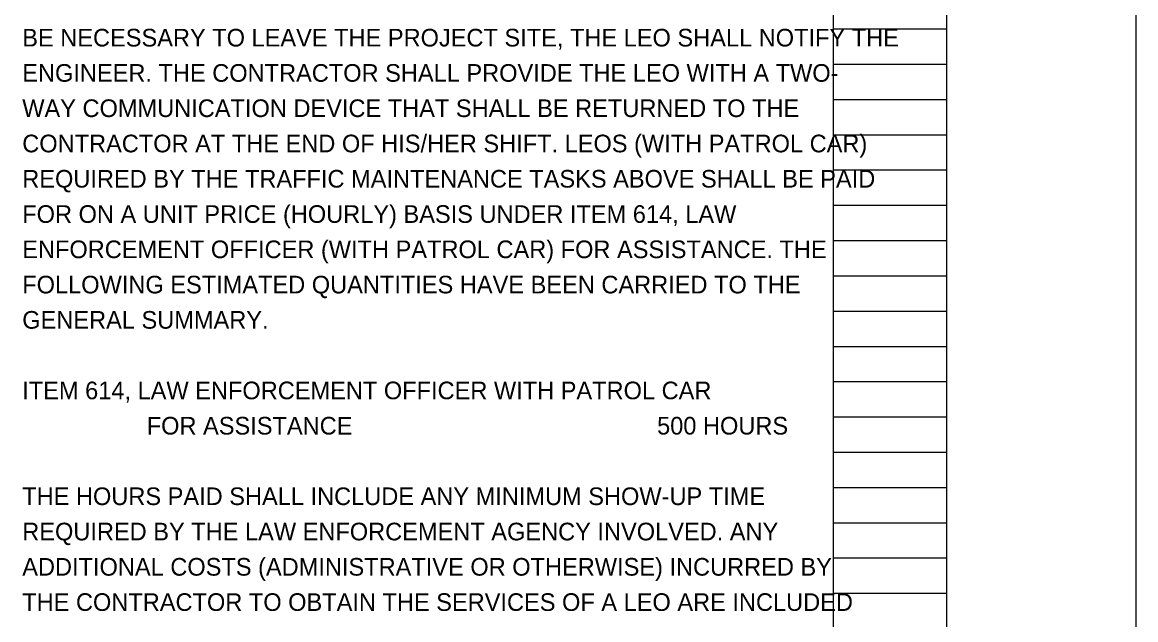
# Model space of a CAD drawing. Extents: x -18.5 to 46, y -14.2 to 42.5.
# Drawn here: x 24.66 to 33.5, y 4.69 to 9.43 of the extents above; entities that cross this region are included whole.
import ezdxf

# ---------------------------------------------------------------- set-up
doc = ezdxf.new("R2010")
doc.units = 0
for name, color, linetype in [('SH_Border', 7, 'Continuous'), ('SH_Data', 7, 'Continuous'), ('SH_Text', 7, 'Continuous')]:
    doc.layers.add(name, color=color, linetype=linetype)

msp = doc.modelspace()

# ---------------------------------------------------------------- linework, layer by layer
at = {"layer": 'SH_Border'}
msp.add_line((32, 0.5), (32, 21.5), dxfattribs=at)
msp.add_lwpolyline([(1.5, 21.5), (33.5, 21.5), (33.5, 0.5), (1.5, 0.5)], close=True, dxfattribs=at)
at = {"layer": 'SH_Data'}
for p, q in [((31.1, 0.98), (31.1, 21.14)), ((32, 0.98), (32, 21.14)), ((31.1, 9.38), (32, 9.38)), ((31.1, 9.1), (32, 9.1)), ((31.1, 8.82), (32, 8.82)), ((31.1, 8.54), (32, 8.54)), ((31.1, 8.26), (32, 8.26)), ((31.1, 7.98), (32, 7.98)), ((31.1, 7.7), (32, 7.7)), ((31.1, 7.42), (32, 7.42)), ((31.1, 7.14), (32, 7.14)), ((31.1, 6.86), (32, 6.86)), ((31.1, 6.58), (32, 6.58)), ((31.1, 6.3), (32, 6.3)), ((31.1, 6.02), (32, 6.02)), ((31.1, 5.74), (32, 5.74)), ((31.1, 5.46), (32, 5.46)), ((31.1, 5.18), (32, 5.18)), ((31.1, 4.9), (32, 4.9))]:
    msp.add_line(p, q, dxfattribs=at)

# ---------------------------------------------------------------- texts
at = {"layer": 'SH_Text'}
for s, p in [('BE NECESSARY TO LEAVE THE PROJECT SITE, THE LEO SHALL NOTIFY THE ', (24.66, 9.24)), ('ENGINEER. THE CONTRACTOR SHALL PROVIDE THE LEO WITH A TWO-', (24.66, 8.96)), ('WAY COMMUNICATION DEVICE THAT SHALL BE RETURNED TO THE ', (24.66, 8.68)), ('CONTRACTOR AT THE END OF HIS/HER SHIFT. LEOS (WITH PATROL CAR) ', (24.66, 8.4)), ('REQUIRED BY THE TRAFFIC MAINTENANCE TASKS ABOVE SHALL BE PAID ', (24.66, 8.12)), ('FOR ON A UNIT PRICE (HOURLY) BASIS UNDER ITEM 614, LAW ', (24.66, 7.84)), ('ENFORCEMENT OFFICER (WITH PATROL CAR) FOR ASSISTANCE. THE ', (24.66, 7.56)), ('FOLLOWING ESTIMATED QUANTITIES HAVE BEEN CARRIED TO THE ', (24.66, 7.28)), ('GENERAL SUMMARY.', (24.66, 7)), ('ITEM 614, LAW ENFORCEMENT OFFICER WITH PATROL CAR', (24.66, 6.44)), ('                   FOR ASSISTANCE     ', (24.66, 6.16)), ('500 HOURS', (29.7, 6.16)), ('THE HOURS PAID SHALL INCLUDE ANY MINIMUM SHOW-UP TIME', (24.66, 5.6)), ('REQUIRED BY THE LAW ENFORCEMENT AGENCY INVOLVED. ANY ', (24.66, 5.32)), ('ADDITIONAL COSTS (ADMINISTRATIVE OR OTHERWISE) INCURRED BY ', (24.66, 5.04)), ('THE CONTRACTOR TO OBTAIN THE SERVICES OF A LEO ARE INCLUDED ', (24.66, 4.76))]:
    msp.add_text(s, height=0.14, dxfattribs=at).set_placement(p)

doc.saveas('drawing.dxf')
